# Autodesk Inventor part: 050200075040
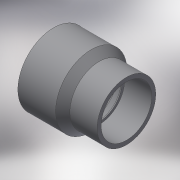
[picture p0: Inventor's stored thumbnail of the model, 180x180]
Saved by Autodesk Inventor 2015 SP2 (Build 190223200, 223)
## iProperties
Created: 2017-10
Part Number: 050200075040
Material: Generic
Description: PLASSON REDUCING SOCKET M.F.75(63)40 CEMENTED
Document SubType Name: Modeling
Designer: KIM
Density: 1 g/cm^3
Appearance: Default
Author: KIM
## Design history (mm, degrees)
derived "050200.ipt"
feature "Solid1::050200.ipt"
tag "TaggingFeature1"
body "Solid1"
other parameters: "d0" = 87, "d1" = 44, "d2" = 26, "d3" = 38, "d5" = 49, "d6" = 63, "d7" = 75, "d8" = 36, "d9" = 6.52847, "d12" = 0.63, "d_" = 63, "L_" = 44, "l_" = 38, "l_1" = 26, "E_" = 49, "H_" = 87, "D_" = 75, "d11" = 6.52847
